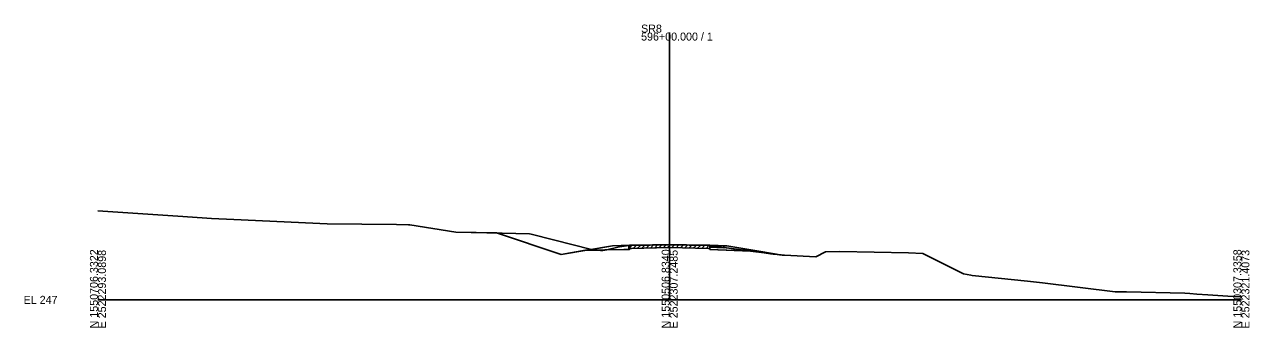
# Model space of a CAD drawing. Extents: x -26 to 2803, y -10 to 19537.
# Drawn here: x -25.7 to 402.8, y 5490.3 to 5596.4 of the extents above; entities that cross this region are included whole.
import ezdxf

# ---------------------------------------------------------------- set-up
doc = ezdxf.new("R2010")
doc.units = 0
for name, color, linetype in [('1', 7, 'Continuous'), ('Draft_XS_Grid', 7, 'Continuous'), ('Draft_XS_Text', 7, 'Continuous'), ('DTM_P_SUBGRADE_1', 7, 'Continuous'), ('DTM_X_GROUND', 7, 'Continuous'), ('SLOPE_STAKES_FILL', 7, 'Continuous'), ('XS_P_ASPHALT', 7, 'Continuous'), ('XS_P_SHOULDER', 7, 'Continuous')]:
    doc.layers.add(name, color=color, linetype=linetype)

msp = doc.modelspace()

# ---------------------------------------------------------------- linework, layer by layer
at = {"layer": '1'}
for p, q in [((200, 5500), (200, 5593.58)), ((0, 5500), (200, 5500)), ((200, 5500), (400, 5500))]:
    msp.add_line(p, q, dxfattribs=at)
at = {"layer": 'Draft_XS_Grid'}
for p, q in [((185.76, 5517.98), (186.78, 5519)), ((185.76, 5517.98), (185.76, 5518.98)), ((185.76, 5517.98), (186.68, 5518)), ((186.68, 5518), (199.68, 5518.31)), ((187.26, 5518.01), (188.28, 5519.04)), ((188.76, 5518.05), (189.78, 5519.07)), ((190.26, 5518.08), (191.28, 5519.11)), ((191.76, 5518.12), (192.78, 5519.14)), ((193.26, 5518.15), (194.28, 5519.18)), ((194.76, 5518.19), (195.78, 5519.21)), ((196.26, 5518.22), (197.28, 5519.25)), ((197.76, 5518.26), (198.78, 5519.28)), ((199.26, 5518.3), (200.25, 5519.29)), ((199.68, 5518.31), (200, 5518.3)), ((200, 5518.3), (213.57, 5517.97)), ((200.76, 5518.28), (201.74, 5519.26)), ((202.26, 5518.24), (203.24, 5519.22)), ((203.76, 5518.21), (204.74, 5519.18)), ((205.26, 5518.17), (206.24, 5519.15)), ((206.76, 5518.14), (207.74, 5519.11)), ((208.26, 5518.1), (209.24, 5519.08)), ((209.76, 5518.06), (210.74, 5519.04)), ((211.26, 5518.03), (212.24, 5519)), ((212.76, 5517.99), (213.74, 5518.97)), ((213.57, 5517.97), (214.03, 5517.96)), ((214.03, 5518.96), (214.03, 5517.96))]:
    msp.add_line(p, q, dxfattribs=at)
at = {"layer": 'Draft_XS_Text'}
for p, q in [((251.1, 5515.1), (254.46, 5516.78)), ((254.46, 5516.78), (259.48, 5516.98)), ((259.48, 5516.98), (271.51, 5516.72)), ((271.51, 5516.72), (283.53, 5516.45)), ((283.53, 5516.45), (288.55, 5516.25)), ((288.55, 5516.25), (302.81, 5509.14))]:
    msp.add_line(p, q, dxfattribs=at)
for points in [[(0, 5531.19), (27.92, 5529.28), (36.49, 5528.69), (39.74, 5528.47), (47.53, 5528.11), (80.22, 5526.6), (104.42, 5526.34), (108.65, 5526.3), (109.11, 5526.23), (125.2, 5523.72), (141.43, 5523.39), (151.01, 5523.09), (151.54, 5522.96), (159.38, 5521), (172.63, 5517.67), (174.71, 5517.38), (175.85, 5517.22), (176.57, 5517.31), (178, 5517.49), (181.88, 5518.47), (182.42, 5518.61), (185.76, 5518.98), (186.68, 5519), (199.68, 5519.31), (200, 5519.3), (213.57, 5518.97), (214.03, 5518.96), (216.97, 5518.59), (217.39, 5518.54), (218.09, 5518.44), (233.05, 5516.44), (235.31, 5516.14), (236.22, 5516.02), (236.71, 5515.95), (240.12, 5515.6), (251.1, 5515.1)], [(302.81, 5509.14), (305.4, 5508.62), (305.85, 5508.57), (325.22, 5506.59), (330.4, 5505.99), (355.84, 5502.84), (357.67, 5502.85), (359.81, 5502.8), (380.22, 5502.29), (381.92, 5502.18), (384.38, 5502.01), (388.25, 5501.76), (395.22, 5501.29), (400, 5501.05)]]:
    msp.add_lwpolyline(points, dxfattribs=at)
at = {"layer": 'DTM_P_SUBGRADE_1'}
for p, q in [((184, 5517.61), (170.59, 5517.34)), ((186, 5517.65), (184, 5517.61)), ((186, 5517.65), (186, 5518.4)), ((214, 5518.4), (214, 5517.65)), ((214, 5517.65), (231.84, 5516.94))]:
    msp.add_line(p, q, dxfattribs=at)
at = {"layer": 'DTM_X_GROUND'}
for p, q in [((162, 5515.91), (139.45, 5523.43)), ((180, 5518.91), (162, 5515.91)), ((186, 5519.15), (180, 5518.91)), ((188, 5519.19), (186, 5519.15)), ((188, 5519.19), (200, 5519.43)), ((200, 5519.43), (212, 5519.19)), ((212, 5519.19), (214, 5519.15)), ((214, 5519.15), (220, 5518.91)), ((220, 5518.91), (239.38, 5515.68))]:
    msp.add_line(p, q, dxfattribs=at)
at = {"layer": 'SLOPE_STAKES_FILL'}
for p, q in [((139.45, 5523.43), (162, 5515.91)), ((162, 5515.91), (180, 5518.91)), ((180, 5518.91), (186, 5519.15)), ((186, 5519.15), (188, 5519.19)), ((188, 5519.19), (200, 5519.43)), ((200, 5519.43), (212, 5519.19)), ((212, 5519.19), (214, 5519.15)), ((214, 5519.15), (220, 5518.91)), ((220, 5518.91), (239.38, 5515.68)), ((251.1, 5515.1), (254.46, 5516.78)), ((254.46, 5516.78), (259.48, 5516.98)), ((259.48, 5516.98), (271.51, 5516.72)), ((271.51, 5516.72), (283.53, 5516.45)), ((283.53, 5516.45), (288.55, 5516.25)), ((288.55, 5516.25), (302.81, 5509.14))]:
    msp.add_line(p, q, dxfattribs=at)
for points in [[(0, 5531.19), (27.92, 5529.28), (36.49, 5528.69), (39.74, 5528.47), (47.53, 5528.11), (80.22, 5526.6), (104.42, 5526.34), (108.65, 5526.3), (109.11, 5526.23), (125.2, 5523.72), (139.45, 5523.43)], [(239.38, 5515.68), (240.12, 5515.6), (251.1, 5515.1)], [(302.81, 5509.14), (305.4, 5508.62), (305.85, 5508.57), (325.22, 5506.59), (330.4, 5505.99), (355.84, 5502.84), (357.67, 5502.85), (359.81, 5502.8), (380.22, 5502.29), (381.92, 5502.18), (384.38, 5502.01), (388.25, 5501.76), (395.22, 5501.29), (400, 5501.05)]]:
    msp.add_lwpolyline(points, dxfattribs=at)
at = {"layer": 'XS_P_ASPHALT'}
for p, q in [((186, 5518.4), (186, 5519.15)), ((214, 5518.4), (214, 5519.15)), ((214, 5518.4), (219, 5518.2)), ((219, 5518.2), (219, 5518.95))]:
    msp.add_line(p, q, dxfattribs=at)
at = {"layer": 'XS_P_SHOULDER'}
for points in [[(141.43, 5523.39), (151.01, 5523.09), (151.54, 5522.96), (159.38, 5521), (172.6, 5517.68), (170.59, 5517.34), (162, 5515.91), (139.45, 5523.43)], [(174.46, 5517.42), (170.59, 5517.34), (172.6, 5517.68), (172.63, 5517.67)], [(182.42, 5518.61), (185.76, 5518.98), (186, 5518.98), (186, 5519.15), (180, 5518.91), (172.6, 5517.68), (172.63, 5517.67), (174.46, 5517.42), (178, 5517.49), (181.88, 5518.47)], [(176.57, 5517.31), (178, 5517.49), (174.46, 5517.42), (174.71, 5517.38), (175.85, 5517.22)], [(182.42, 5518.61), (185.76, 5518.98), (185.76, 5517.98), (186, 5517.98), (186, 5517.65), (184, 5517.61), (178, 5517.49), (181.88, 5518.47)], [(185.76, 5517.98), (186, 5517.98), (186, 5518.4), (186, 5518.98), (185.76, 5518.98)], [(200, 5519.43), (212, 5519.19), (214, 5519.15), (214, 5518.96), (213.57, 5518.97), (200, 5519.3), (199.68, 5519.31), (186.68, 5519), (186, 5518.98), (186, 5519.15), (188, 5519.19)], [(214, 5518.96), (214.03, 5518.96), (216.97, 5518.59), (217.39, 5518.54), (218.09, 5518.44), (219, 5518.32), (219, 5518.95), (214, 5519.15)], [(214, 5517.65), (228.29, 5517.08), (219, 5518.32), (219, 5518.2), (214.03, 5518.4), (214.03, 5517.96), (214, 5517.96)], [(214.03, 5518.4), (219, 5518.2), (219, 5518.32), (218.09, 5518.44), (217.39, 5518.54), (216.97, 5518.59), (214.03, 5518.96)], [(219, 5518.95), (220, 5518.91), (231.84, 5516.94), (228.29, 5517.08), (219, 5518.32)], [(228.29, 5517.08), (233.05, 5516.44), (235.31, 5516.14), (236.22, 5516.02), (236.71, 5515.95), (239.38, 5515.68), (231.84, 5516.94)]]:
    msp.add_lwpolyline(points, close=True, dxfattribs=at)

# ---------------------------------------------------------------- texts
at = {"layer": '1'}
for s, p in [('596+00.000 / 1', (190, 5590.78)), ('SR8', (190, 5593.58)), ('EL 247', (-26, 5498.6))]:
    msp.add_text(s, height=2.8, dxfattribs=at).set_placement(p)
for s, p in [('N 1550706.3322', (0, 5490)), ('E 2522293.0898', (2.8, 5490)), ('N 1550506.8340', (200, 5490)), ('E 2522307.2485', (202.8, 5490)), ('N 1550307.3358', (400, 5490)), ('E 2522321.4073', (402.8, 5490))]:
    msp.add_text(s, height=2.8, rotation=90, dxfattribs=at).set_placement(p)

doc.saveas('drawing.dxf')
